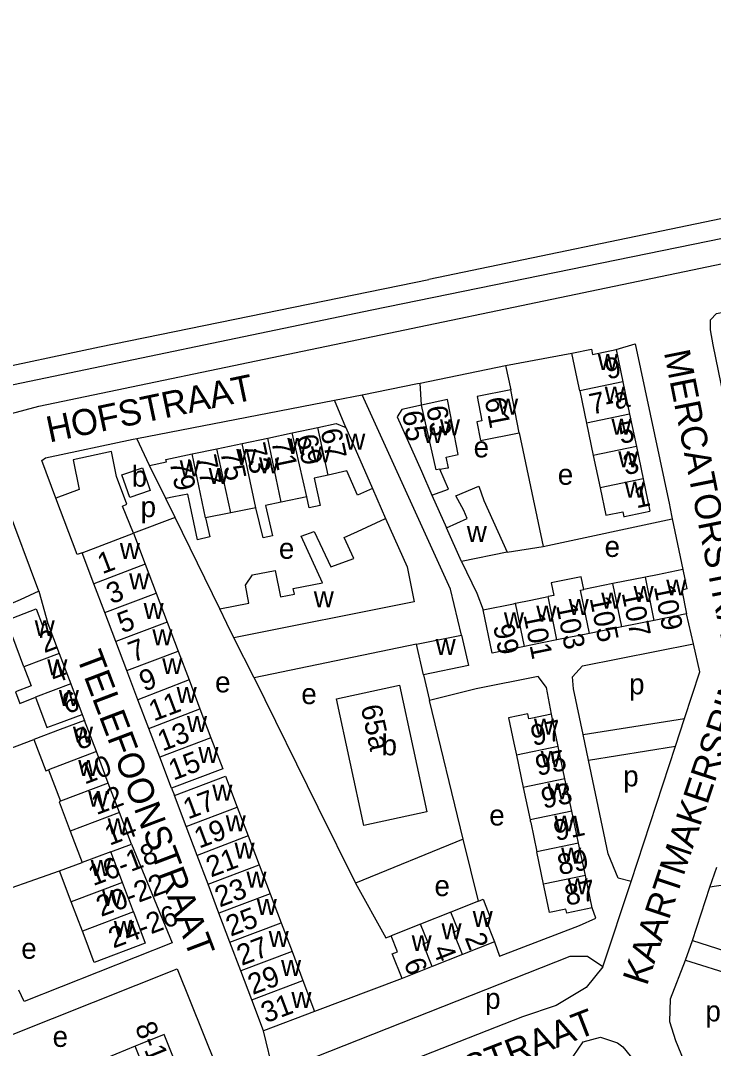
# Model space of a CAD drawing. Extents: x 163026 to 166241, y 382475 to 384501.
# Drawn here: x 163901.8 to 164035.2, y 384015.1 to 384213 of the extents above; entities that cross this region are included whole.
import ezdxf

# ---------------------------------------------------------------- set-up
doc = ezdxf.new("R2010")
doc.units = 0
for name, color, linetype in [('BLT_Basislijn', 7, 'Continuous'), ('BLT_Bebouwing', 7, 'Continuous'), ('BLT_Centroide', 7, 'Continuous'), ('BLT_Huisnummer', 7, 'Continuous'), ('BLT_Huisnummer_ tussenligend', 7, 'Continuous'), ('BLT_Huisnummer_reeks', 7, 'Continuous'), ('BLT_Onderverdeling_panden', 7, 'Continuous'), ('BLT_Spoorlijn', 7, 'Continuous'), ('BLT_Straatnaam', 7, 'Continuous')]:
    doc.layers.add(name, color=color, linetype=linetype)

msp = doc.modelspace()

# ---------------------------------------------------------------- linework, layer by layer
at = {"layer": 'BLT_Basislijn'}
for p, q in [((163969.43, 384157.19), (163890.65, 384140.81)), ((163995.18, 384146.58), (164007.9, 384148.93)), ((163978.76, 384143.19), (163995.18, 384146.58)), ((163995.18, 384146.58), (163996.19, 384141.86)), ((163978.99, 384138.9), (163978.76, 384143.19)), ((163924.2, 384132.51), (163962.27, 384139.91)), ((163962.27, 384139.91), (163967.6, 384140.94)), ((163964.4, 384134.65), (163962.27, 384139.91)), ((163997.79, 384133.57), (164002.41, 384111.74)), ((163923.51, 384132.38), (163924.2, 384132.51)), ((163926.63, 384127.33), (163924.2, 384132.51)), ((163969.56, 384122.87), (163972.09, 384117.11)), ((163981, 384121.59), (163983.78, 384115.33)), ((163931.59, 384117.3), (163929.82, 384120.93)), ((164026.77, 384119.36), (164027.26, 384117.06)), ((163931.59, 384117.3), (163923.54, 384114.25)), ((163940.2, 384099.68), (163931.59, 384117.3)), ((164002.41, 384111.74), (164027.26, 384117.06)), ((164027.26, 384117.06), (164029.31, 384107.26)), ((163905.38, 384103.11), (163907.07, 384096.9)), ((164031.31, 384092.97), (164030.01, 384098.74)), ((163946.76, 384086.4), (163942.85, 384094.13)), ((163978.06, 384092.88), (163946.76, 384086.4)), ((163946.76, 384086.4), (163959.06, 384061.5)), ((163979.37, 384087.02), (163980.5, 384082.08)), ((163987.03, 384055.33), (163980.5, 384082.08)), ((163913.7, 384079.39), (163914.17, 384078.2)), ((164010.07, 384075.5), (164029.59, 384078.6)), ((164027.84, 384073.26), (164029.59, 384078.6)), ((164011.1, 384070.6), (164010.07, 384075.5)), ((164011.1, 384070.6), (164027.84, 384073.26)), ((164019.32, 384047.21), (164027.84, 384073.26)), ((163930.89, 384065.16), (163931.44, 384063.77)), ((163959.06, 384061.5), (163966.29, 384046.88)), ((163987.03, 384055.33), (163966.29, 384046.88)), ((163989.93, 384043.43), (163987.03, 384055.33)), ((164034.48, 384046.13), (164035.81, 384049.95)), ((164013.9, 384030.78), (164019.32, 384047.21)), ((164031.13, 384035.86), (164034.48, 384046.13)), ((164029.78, 384032.09), (164031.13, 384035.86))]:
    msp.add_line(p, q, dxfattribs=at)
for points in [[(163900.11, 384137.3), (163905.37, 384138.71), (164182.17, 384196.48), (164249.9, 384212.98), (164253.88, 384212.82), (164257.32, 384211.62), (164261.05, 384208.36), (164262.81, 384205.4), (164265.99, 384192.34), (164268.94, 384175.29), (164269.89, 384164.18), (164270.1, 384149.11), (164272.14, 384146.86), (164275.23, 384146.44), (164277.11, 384147)], [(164041.64, 384118.16), (164036.68, 384143.01), (164035.15, 384150.54), (164034.58, 384153.44), (164034.61, 384155.37), (164035.79, 384156.58), (164112.52, 384172.6), (164235.89, 384198.32), (164241.09, 384199.14)], [(164153.55, 384195.58), (164063.6, 384176.49), (163969.43, 384157.19)], [(164016.43, 384149.64), (164020.14, 384150.71), (164026.7, 384119.71), (164026.77, 384119.36)], [(163967.6, 384140.94), (163978.2, 384143.07), (163978.76, 384143.19)], [(163986.72, 384094.62), (163984.55, 384103.48), (163967.6, 384140.94)], [(163908.65, 384121.02), (163905.92, 384128.28), (163906.65, 384128.81), (163923.51, 384132.38)], [(163923.54, 384114.25), (163921.43, 384119.5), (163922.3, 384119.85), (163920.31, 384125.16), (163919.31, 384130.01), (163911.93, 384128.42), (163913.13, 384122.66), (163908.65, 384121.02)], [(163913.66, 384110.51), (163912.73, 384110.16), (163908.65, 384121.02)], [(163995.49, 384110.65), (164002.41, 384111.74)], [(163986.67, 384108.79), (163989.62, 384102.71), (163990.88, 384099.5)], [(164010.07, 384075.5), (164008.22, 384084.3), (164008.06, 384086.62), (164009.98, 384088.76), (164031.31, 384092.97)], [(164029.59, 384078.6), (164032.53, 384087.58), (164031.31, 384092.97)], [(164003.99, 384079.41), (164003.02, 384084.55), (164001.47, 384086.66), (163989.5, 384084.32), (163980.5, 384082.08)], [(163897.43, 384071.44), (163897.96, 384072.12), (163904.4, 384074.58)], [(164019.32, 384047.21), (164016.86, 384047.86), (164014.9, 384052.51), (164011.1, 384070.6)], [(163923.18, 384054.38), (163930.98, 384035.41), (163902.51, 384024.13), (163901.48, 384026.31)], [(163893.52, 384043.92), (163894.32, 384043.98), (163909.33, 384049.29)], [(163966.29, 384046.88), (163972.15, 384036.37), (163973.15, 384036.77)], [(164031.13, 384035.86), (164042.2, 384032.3), (164042.9, 384032.41), (164040.48, 384043.21), (164039.76, 384045.91), (164039.23, 384046.82), (164034.48, 384046.13)], [(163993.04, 384035.59), (163993.99, 384032.84), (164009.4, 384038.71), (164012.56, 384040.16), (164011.82, 384042.16)], [(164013.9, 384030.78), (164010.95, 384032.79), (164007.52, 384032.76), (163950.57, 384010.22)], [(164013.9, 384030.78), (164010.71, 384026.83), (164004.88, 384023.36), (163998.44, 384021.13), (163960.21, 384006.11), (163957.71, 384005.31), (163955, 384005.21), (163952.82, 384006.26), (163951.27, 384008.13), (163950.57, 384010.22)], [(164033.5, 384002.94), (164027.93, 384016.56), (164026.77, 384020.21), (164026.93, 384024.62), (164029.78, 384032.09)], [(164029.78, 384032.09), (164039.23, 384029.1), (164043.1, 384027.73), (164044.22, 384027.03), (164050.23, 384000.8), (164049.59, 384000.67), (164033.5, 384002.94)], [(163891.79, 384014.44), (163932, 384030.42), (163939.47, 384011.72), (163939.8, 384010.54)], [(163975.26, 384028.54), (163958.43, 384022.19)], [(163950.57, 384010.22), (163948.6, 384018.46)], [(163951.25, 383989.73), (163966.03, 383997.1), (164006.98, 384012.75), (164008.16, 384013.54), (164010.07, 384016.33), (164013.42, 384017.21), (164016.7, 384016.16), (164017.72, 384015.36), (164020.53, 384011.89), (164021.01, 384009.61), (164020.21, 384007.33), (164053.12, 383922.18), (164053.94, 383920.34), (164056.04, 383918.89), (164056.89, 383917.77), (164057.24, 383913.87), (164056.6, 383912.2), (164054.53, 383910.44), (164053.37, 383909.9)]]:
    msp.add_lwpolyline(points, dxfattribs=at)
at = {"layer": 'BLT_Bebouwing'}
for p, q in [((164016.43, 384149.64), (164017.73, 384143.42)), ((164017.73, 384143.42), (164019.04, 384137.19)), ((163997.79, 384133.57), (163996.19, 384141.86)), ((164009.43, 384141.68), (164010.74, 384135.45)), ((164010.74, 384135.45), (164012.04, 384129.22)), ((164019.04, 384137.19), (164020.35, 384130.96)), ((163949.39, 384132.6), (163954.12, 384133.6)), ((163954.12, 384133.6), (163959.06, 384134.64)), ((163964.4, 384134.65), (163969.56, 384122.87)), ((163939.6, 384130.53), (163944.48, 384131.56)), ((163944.48, 384131.56), (163949.39, 384132.6)), ((163934.83, 384129.52), (163939.6, 384130.53)), ((164020.35, 384130.96), (164021.66, 384124.74)), ((164012.04, 384129.22), (164013.35, 384122.99)), ((164021.66, 384124.74), (164022.96, 384118.51)), ((164013.35, 384122.99), (164014.45, 384117.73)), ((163905.38, 384103.11), (163899.1, 384119.78)), ((163956.9, 384121.29), (163952.01, 384120.24)), ((163966.65, 384114.58), (163972.09, 384117.11)), ((163913.66, 384110.51), (163923.54, 384114.25)), ((163923.54, 384114.25), (163925.8, 384108.29)), ((163986.67, 384108.79), (163983.78, 384115.33)), ((163915.93, 384104.54), (163913.66, 384110.51)), ((163995.49, 384110.65), (163986.67, 384108.79)), ((163925.8, 384108.29), (163927.91, 384102.72)), ((164022.08, 384105.81), (164015.84, 384104.56)), ((163918.05, 384098.97), (163915.93, 384104.54)), ((164015.84, 384104.56), (164010.2, 384103.42)), ((163927.91, 384102.72), (163930.03, 384097.15)), ((163920.16, 384093.4), (163918.05, 384098.97)), ((163941.53, 384096.88), (163940.2, 384099.68)), ((164030.01, 384098.74), (164023.77, 384097.48)), ((163907.07, 384096.9), (163909.26, 384091.12)), ((163930.03, 384097.15), (163932.14, 384091.58)), ((163942.85, 384094.13), (163941.53, 384096.88)), ((164017.53, 384096.23), (164011.29, 384094.97)), ((164023.77, 384097.48), (164017.53, 384096.23)), ((163978.06, 384092.88), (163986.72, 384094.62)), ((164011.29, 384094.97), (164005.05, 384093.72)), ((163922.28, 384087.83), (163920.16, 384093.4)), ((163979.37, 384087.02), (163978.06, 384092.88)), ((163909.26, 384091.12), (163911.48, 384085.26)), ((163932.14, 384091.58), (163934.25, 384086.01)), ((163924.42, 384082.19), (163922.28, 384087.83)), ((163934.25, 384086.01), (163936.36, 384080.43)), ((163911.48, 384085.26), (163913.7, 384079.39)), ((163926.51, 384076.69), (163924.42, 384082.19)), ((163936.36, 384080.43), (163938.48, 384074.86)), ((163916.42, 384072.25), (163914.17, 384078.2)), ((164005.3, 384073.2), (164003.99, 384079.41)), ((163928.62, 384071.12), (163926.51, 384076.69)), ((163938.48, 384074.86), (163940.74, 384068.89)), ((163918.72, 384066.16), (163916.42, 384072.25)), ((164006.6, 384066.99), (164005.3, 384073.2)), ((163930.89, 384065.16), (163928.62, 384071.12)), ((163997.27, 384071.51), (163998.58, 384065.31)), ((163907.2, 384068.72), (163909.49, 384062.66)), ((163940.74, 384068.89), (163930.89, 384065.16)), ((163920.87, 384060.49), (163918.72, 384066.16)), ((163931.44, 384063.77), (163941.27, 384067.51)), ((163941.27, 384067.51), (163943.54, 384061.53)), ((164007.91, 384060.78), (164006.6, 384066.99)), ((163998.58, 384065.31), (163999.89, 384059.1)), ((163933.7, 384057.81), (163931.44, 384063.77)), ((163923.18, 384054.38), (163920.87, 384060.49)), ((163943.54, 384061.53), (163945.64, 384055.97)), ((164009.21, 384054.58), (164007.91, 384060.78)), ((163911.39, 384056.9), (163913.67, 384050.88)), ((163935.81, 384052.24), (163933.7, 384057.81)), ((163919.19, 384052.91), (163923.18, 384054.38)), ((163945.64, 384055.97), (163947.75, 384050.41)), ((164010.52, 384048.37), (164009.21, 384054.58)), ((163921.42, 384047.04), (163919.19, 384052.91)), ((164002.49, 384046.68), (164001.19, 384052.89)), ((163909.33, 384049.29), (163913.67, 384050.88)), ((163937.91, 384046.68), (163935.81, 384052.24)), ((163947.75, 384050.41), (163949.86, 384044.84)), ((163911.59, 384043.32), (163909.33, 384049.29)), ((164011.82, 384042.16), (164010.52, 384048.37)), ((163923.57, 384041.35), (163921.42, 384047.04)), ((163940.02, 384041.12), (163937.91, 384046.68)), ((163949.86, 384044.84), (163951.96, 384039.28)), ((163913.74, 384037.63), (163911.59, 384043.32)), ((163989.93, 384043.43), (163984.64, 384041.33)), ((163942.12, 384035.55), (163940.02, 384041.12)), ((163984.64, 384041.33), (163978.83, 384039.02)), ((163951.96, 384039.28), (163954.07, 384033.72)), ((163978.83, 384039.02), (163973.15, 384036.77)), ((163944.23, 384029.99), (163942.12, 384035.55)), ((163993.04, 384035.59), (163986.85, 384033.13)), ((163954.07, 384033.72), (163956.18, 384028.15)), ((163986.85, 384033.13), (163981.04, 384030.83)), ((163981.04, 384030.83), (163975.26, 384028.54)), ((163946.34, 384024.43), (163944.23, 384029.99)), ((163956.18, 384028.15), (163958.43, 384022.19)), ((163948.6, 384018.46), (163946.34, 384024.43)), ((163958.43, 384022.19), (163948.6, 384018.46)), ((163923.89, 384015.48), (163918.32, 384013.22))]:
    msp.add_line(p, q, dxfattribs=at)
for points in [[(164007.9, 384148.93), (164011.68, 384149.73), (164011.89, 384148.69), (164016.43, 384149.64)], [(164009.43, 384141.68), (164008.92, 384144.08), (164007.9, 384148.93)], [(163996.19, 384141.86), (163989.68, 384140.6), (163990.59, 384135.91), (163989.66, 384135.73), (163990.35, 384132.13), (163997.79, 384133.57)], [(163982.51, 384126.59), (163983.98, 384126.84), (163984.18, 384126.87), (163983.74, 384128.89), (163986.07, 384129.4), (163984.97, 384135.08), (163984.02, 384140), (163978.99, 384138.9)], [(163978.99, 384138.9), (163975.2, 384138.07), (163974.32, 384136.7), (163978.96, 384126.2), (163981, 384121.59)], [(163959.06, 384134.64), (163962.54, 384135.38), (163964.4, 384134.65)], [(163926.63, 384127.33), (163929.9, 384128.02), (163929.81, 384128.46), (163934.83, 384129.52)], [(163929.82, 384120.93), (163926.63, 384127.33)], [(163969.56, 384122.87), (163966.65, 384121.59), (163964.6, 384126.26), (163961.03, 384125.46)], [(163981, 384121.59), (163984.21, 384122.73), (163982.51, 384126.59)], [(163961.03, 384125.46), (163958.35, 384124.85), (163959.52, 384119.62), (163957.38, 384119.14), (163956.9, 384121.29)], [(163937.43, 384117.2), (163938.28, 384113.54), (163935.87, 384112.99), (163934, 384121.8), (163931.35, 384121.25), (163929.82, 384120.93)], [(163983.78, 384115.33), (163987.77, 384117.11), (163987.14, 384118.61), (163985.62, 384121.45), (163990.02, 384123.35), (163990.98, 384120.54), (163995.49, 384110.65)], [(163952.01, 384120.24), (163948.99, 384119.58), (163950.34, 384113.79), (163948.55, 384113.38), (163947.1, 384119.18)], [(163942.33, 384118.2), (163937.43, 384117.2)], [(163947.1, 384119.18), (163942.33, 384118.2)], [(164014.45, 384117.73), (164017.71, 384118.41), (164017.91, 384117.45), (164018.07, 384117.48), (164022.96, 384118.51)], [(163972.09, 384117.11), (163976.21, 384107.78), (163977.56, 384101.07), (163942.85, 384094.13)], [(163905.38, 384103.11), (163901.76, 384101.43), (163893.77, 384098.05), (163890.52, 384105.5), (163894.14, 384107.07), (163893.02, 384109.64), (163896.61, 384111.21), (163895.4, 384113.89)], [(163940.2, 384099.68), (163945.79, 384100.8), (163945.1, 384104.28), (163946.44, 384106.24), (163950.84, 384107.12), (163951.86, 384102.01), (163954.52, 384102.55), (163954.31, 384103.61), (163959.94, 384104.74), (163955.85, 384113.7), (163958.35, 384114.58), (163961.52, 384107.8), (163965.95, 384109.41), (163964.11, 384113.47), (163966.65, 384114.58)], [(164010.2, 384103.42), (164009.7, 384105.89), (164003.96, 384104.73), (164004.46, 384102.26), (164003.35, 384102.06)], [(164029.31, 384107.26), (164024.41, 384106.28), (164022.08, 384105.81)], [(164029.31, 384107.26), (164030.08, 384103.53), (164029.07, 384103.32), (164030.01, 384098.74)], [(163997.11, 384100.79), (164000, 384101.39), (164003.35, 384102.06)], [(163990.88, 384099.5), (163996.68, 384100.7), (163997.11, 384100.79)], [(163902.48, 384088.55), (163900.33, 384094.23), (163899.15, 384093.78), (163897.91, 384097.05), (163899.83, 384097.77), (163900.2, 384097.91), (163904.87, 384099.68), (163906.07, 384096.52), (163907.07, 384096.9)], [(163998.81, 384092.45), (163992.58, 384091.14), (163990.88, 384099.5)], [(163986.72, 384094.62), (163988.03, 384088.82), (163979.37, 384087.02)], [(164005.05, 384093.72), (164000, 384092.7), (163998.81, 384092.45)], [(163902.48, 384088.55), (163903.87, 384084.89), (163900.85, 384083.74), (163901.7, 384081.5), (163904.7, 384082.69)], [(163962.61, 384082.37), (163974.76, 384085), (163980.02, 384060.63), (163967.88, 384058.01), (163962.61, 384082.37)], [(163904.7, 384082.69), (163906.92, 384076.83), (163909.02, 384077.62), (163913.7, 384079.39)], [(163914.17, 384078.2), (163909.47, 384076.48), (163904.4, 384074.58)], [(164003.99, 384079.41), (164000, 384078.58), (163999.63, 384078.5), (163999.43, 384079.51), (163995.75, 384078.74), (163996.77, 384073.85), (163997.27, 384071.51)], [(163904.4, 384074.58), (163906.69, 384068.53), (163907.2, 384068.72)], [(163909.49, 384062.66), (163909.24, 384062.57), (163911.39, 384056.9)], [(163999.89, 384059.1), (163999.93, 384058.88), (163999.97, 384058.72), (164000, 384058.56), (164001.19, 384052.89)], [(164011.82, 384042.16), (164006.95, 384041.13), (164006.78, 384041.91), (164003.63, 384041.24), (164002.61, 384046.14), (164002.49, 384046.68)], [(163989.93, 384043.43), (163990.83, 384043.79), (163992.22, 384040.3), (163991.31, 384039.94), (163993.04, 384035.59)], [(163923.57, 384041.35), (163925.84, 384035.36), (163916.01, 384031.64), (163914.24, 384036.32), (163913.74, 384037.63)], [(163975.26, 384028.54), (163973.42, 384033.18), (163973.37, 384033.3), (163974.35, 384033.68), (163973.15, 384036.77)], [(163933.41, 384008.02), (163929.46, 384017.74), (163924.83, 384015.86), (163923.89, 384015.48)]]:
    msp.add_lwpolyline(points, dxfattribs=at)
msp.add_lwpolyline([(163921.35, 384125.51), (163925.27, 384126.85), (163926.76, 384122.49), (163922.84, 384121.15)], close=True, dxfattribs=at)
at = {"layer": 'BLT_Onderverdeling_panden'}
for p, q in [((164017.73, 384143.42), (164009.43, 384141.68)), ((164019.04, 384137.19), (164010.74, 384135.45)), ((163956.9, 384121.29), (163954.12, 384133.6)), ((163961.03, 384125.46), (163959.06, 384134.64)), ((163947.1, 384119.18), (163944.48, 384131.56)), ((163952.01, 384120.24), (163949.39, 384132.6)), ((163937.43, 384117.2), (163934.83, 384129.52)), ((163942.33, 384118.2), (163939.6, 384130.53)), ((164020.35, 384130.96), (164012.04, 384129.22)), ((164021.66, 384124.74), (164013.35, 384122.99)), ((163925.8, 384108.29), (163915.93, 384104.54)), ((164023.77, 384097.48), (164022.08, 384105.81)), ((164017.53, 384096.23), (164015.84, 384104.56)), ((163918.05, 384098.97), (163927.91, 384102.72)), ((164005.05, 384093.72), (164003.35, 384102.06)), ((163998.81, 384092.45), (163997.11, 384100.79)), ((163930.03, 384097.15), (163920.16, 384093.4)), ((163909.26, 384091.12), (163902.48, 384088.55)), ((163922.28, 384087.83), (163932.14, 384091.58)), ((163934.25, 384086.01), (163924.42, 384082.19)), ((163911.48, 384085.26), (163904.7, 384082.69)), ((163926.51, 384076.69), (163936.36, 384080.43)), ((163938.48, 384074.86), (163928.62, 384071.12)), ((163916.42, 384072.25), (163907.2, 384068.72)), ((164005.3, 384073.2), (163997.27, 384071.51)), ((163918.72, 384066.16), (163909.49, 384062.66)), ((164006.6, 384066.99), (163998.58, 384065.31)), ((163920.87, 384060.49), (163911.39, 384056.9)), ((163933.7, 384057.81), (163943.54, 384061.53)), ((164007.91, 384060.78), (163999.89, 384059.1)), ((163945.64, 384055.97), (163935.81, 384052.24)), ((164009.21, 384054.58), (164001.19, 384052.89)), ((163919.19, 384052.91), (163913.67, 384050.88)), ((163937.91, 384046.68), (163947.75, 384050.41)), ((164010.52, 384048.37), (164002.49, 384046.68)), ((163921.42, 384047.04), (163911.59, 384043.32)), ((163949.86, 384044.84), (163940.02, 384041.12)), ((163923.57, 384041.35), (163913.74, 384037.63)), ((163942.12, 384035.55), (163951.96, 384039.28)), ((163954.07, 384033.72), (163944.23, 384029.99)), ((163946.34, 384024.43), (163956.18, 384028.15)), ((163927.83, 384005.75), (163923.89, 384015.48))]:
    msp.add_line(p, q, dxfattribs=at)
for points in [[(163982.51, 384126.59), (163981.79, 384126.47), (163978.99, 384138.9)], [(164011.29, 384094.97), (164009.59, 384103.31), (164010.2, 384103.42)], [(163986.85, 384033.13), (163985.12, 384037.48), (163986.02, 384037.84), (163984.64, 384041.33)], [(163981.04, 384030.83), (163979.31, 384035.18), (163980.22, 384035.54), (163978.83, 384039.02)]]:
    msp.add_lwpolyline(points, dxfattribs=at)
at = {"layer": 'BLT_Spoorlijn'}
for points in [[(164154.58, 384199.32), (163980.39, 384163.11)], [(163894.03, 384145.25), (163917.02, 384150.14), (163980.39, 384163.11)]]:
    msp.add_lwpolyline(points, dxfattribs=at)

# ---------------------------------------------------------------- texts
at = {"layer": 'BLT_Centroide'}
for s, p in [('w', (164012.91, 384145.69)), ('w', (164014.24, 384139.44)), ('w', (163993.72, 384137.08)), ('w', (163982.53, 384133.14)), ('w', (164015.54, 384133.22)), ('w', (163979.27, 384131.61)), ('w', (163953.17, 384129.5)), ('w', (163964.31, 384130.34)), ('e', (163989.02, 384128.87)), ('w', (163943.34, 384127.41)), ('w', (163957.7, 384127.91)), ('w', (164016.85, 384126.97)), ('w', (163932.45, 384125.25)), ('w', (163947.72, 384125.78)), ('b', (163923.23, 384123.23)), ('w', (163938.02, 384123.75)), ('e', (164005.22, 384123.59)), ('w', (164018.09, 384121.09)), ('p', (163924.94, 384117.36)), ('w', (163987.71, 384112.6)), ('w', (163920.94, 384109.32)), ('e', (163951.55, 384109.34)), ('e', (164014.22, 384109.7)), ('w', (163922.73, 384103.45)), ('w', (164019.8, 384101.02)), ('w', (164026.08, 384102.28)), ('w', (163958.26, 384100.02)), ('w', (164013.56, 384099.77)), ('w', (163925.51, 384097.78)), ('w', (164001.08, 384097.25)), ('w', (164007.31, 384098.52)), ('w', (163994.84, 384095.97)), ('w', (163904.55, 384094.45)), ('w', (163927.2, 384092.7)), ('w', (163981.71, 384090.81)), ('w', (163906.98, 384086.91)), ('w', (163929.09, 384087.13)), ('e', (163939.27, 384083.62)), ('p', (164018.94, 384083.24)), ('w', (163909.2, 384081.03)), ('w', (163931.87, 384081.56)), ('e', (163955.86, 384081.36)), ('w', (163933.86, 384075.99)), ('w', (164000.62, 384075.5)), ('w', (163911.91, 384073.94)), ('b', (163971.31, 384071.5)), ('w', (163936.05, 384070.02)), ('w', (164001.94, 384069.25)), ('w', (163912.93, 384067.53)), ('p', (164017.81, 384065.52)), ('w', (163914.84, 384061.59)), ('w', (163938.74, 384062.76)), ('w', (164003.24, 384063.03)), ('e', (163992.03, 384057.98)), ('w', (163918.59, 384056.31)), ('w', (163941.32, 384056.89)), ('w', (164004.55, 384056.84)), ('w', (163943.01, 384051.62)), ('w', (164005.86, 384050.62)), ('w', (163915.34, 384048.25)), ('w', (163945.3, 384046.05)), ('e', (163981.48, 384044.4)), ('w', (164007.09, 384044.75)), ('w', (163917.52, 384042.47)), ('w', (163947.29, 384040.78)), ('w', (163988.84, 384038.47)), ('w', (163919.79, 384036.5)), ('w', (163982.84, 384036.08)), ('w', (163949.58, 384034.61)), ('w', (163977.09, 384033.8)), ('e', (163901.97, 384032.33)), ('w', (163951.96, 384029.04)), ('w', (163953.95, 384022.87)), ('p', (163991.24, 384022.68)), ('p', (164033.63, 384020.27)), ('e', (163908, 384015.36))]:
    msp.add_text(s, height=4, dxfattribs=at).set_placement(p)
at = {"layer": 'BLT_Huisnummer'}
for s, rotation, p in [('9', 11.8567, (164014.76, 384143.86)), ('61', 280.929, (163991.11, 384140.11)), ('65', 279.435, (163975.25, 384137.58)), ('63', 279.435, (163979.89, 384138.54)), ('5', 11.8567, (164017.34, 384131.42)), ('67', 281.9355, (163959.53, 384134.04)), ('71', 281.9366, (163950.06, 384131.94)), ('75', 281.9283, (163940.24, 384129.91)), ('79', 281.9371, (163930.48, 384127.97)), ('1', 11.8538, (164020.35, 384119.05)), ('1', 20.6485, (163917.57, 384106.35)), ('109', 281.476, (164023.68, 384103.97)), ('103', 281.4741, (164004.87, 384100.36)), ('5', 20.6485, (163921.39, 384094.96)), ('99', 281.4798, (163992.75, 384096.42)), ('2', 20.7272, (163906.4, 384091.15)), ('9', 20.6485, (163925.61, 384083.73)), ('6', 20.7224, (163910.76, 384079.36)), ('65a', 282.197, (163967.27, 384080.85)), ('97', 11.866, (164000.45, 384073.3)), ('13', 20.6485, (163929.14, 384072.23)), ('10', 20.732, (163914.17, 384065.85)), ('17', 20.6485, (163934.06, 384059.13)), ('14', 20.7266, (163918.96, 384054.07)), ('91', 11.8692, (164004.87, 384054.98)), ('21', 20.6485, (163938.46, 384047.96)), ('87', 11.8602, (164006.99, 384042.52)), ('25', 20.6485, (163942.27, 384036.57)), ('2', 291.6411, (163987.25, 384036.42)), ('6', 291.6513, (163975.5, 384031.59)), ('31', 20.6485, (163949.04, 384019.89))]:
    msp.add_text(s, height=4, rotation=rotation, dxfattribs=at).set_placement(p)
at = {"layer": 'BLT_Huisnummer_ tussenligend'}
for s, rotation, p in [('73', 281.9366, (163944.92, 384131.26)), ('69', 281.9355, (163954.91, 384132.91)), ('77', 281.9283, (163935.47, 384128.94)), ('3', 11.8538, (164018.23, 384125.42)), ('3', 20.6485, (163919.27, 384100.57)), ('105', 281.4741, (164011.32, 384101.76)), ('107', 281.4741, (164017.49, 384102.76)), ('101', 281.4798, (163998.58, 384098.54)), ('7', 20.6485, (163923.49, 384089.34)), ('4', 20.7272, (163908.35, 384085.25)), ('11', 20.6485, (163927.45, 384078.01)), ('8', 20.7224, (163913.15, 384072.49)), ('15', 20.6485, (163931.26, 384066.62)), ('95', 11.8692, (164001.35, 384067.52)), ('93', 11.8692, (164002.47, 384061.2)), ('12', 20.732, (163916.43, 384059.96)), ('19', 20.6485, (163936.19, 384053.52)), ('89', 11.8602, (164005.59, 384048.41)), ('23', 20.6485, (163940.15, 384042.19)), ('27', 20.6485, (163944.37, 384030.95)), ('4', 291.6411, (163981.07, 384034.18)), ('29', 20.6485, (163946.5, 384025.34))]:
    msp.add_text(s, height=4, rotation=rotation, dxfattribs=at).set_placement(p)
at = {"layer": 'BLT_Huisnummer_reeks'}
for s, rotation, p in [('7-a', 11.8567, (164011.74, 384137.09)), ('16-18', 20.7239, (163915.8, 384046.29)), ('20-22', 20.7239, (163917.33, 384040.36)), ('24-26', 20.7309, (163919.69, 384034.28)), ('8-10-12', 292.1015, (163923.78, 384019.25))]:
    msp.add_text(s, height=4, rotation=rotation, dxfattribs=at).set_placement(p)
at = {"layer": 'BLT_Straatnaam'}
for s, height, rotation, p in [('MERCATORSTRAAT', 5, 281.2957, (164025.62, 384149.1)), ('HOFSTRAAT', 5, 11.8754, (163907.38, 384131.71)), ('TELEFOONSTRAAT', 5, 290.7541, (163912.52, 384090.54)), ('KAARTMAKERSRING', 4.9999, 71.5728, (164022.35, 384026.97)), ('LOCOMOTIEFSTRAAT', 5, 21.2193, (163947.1, 383992.65))]:
    msp.add_text(s, height=height, rotation=rotation, dxfattribs=at).set_placement(p)

doc.saveas('drawing.dxf')
